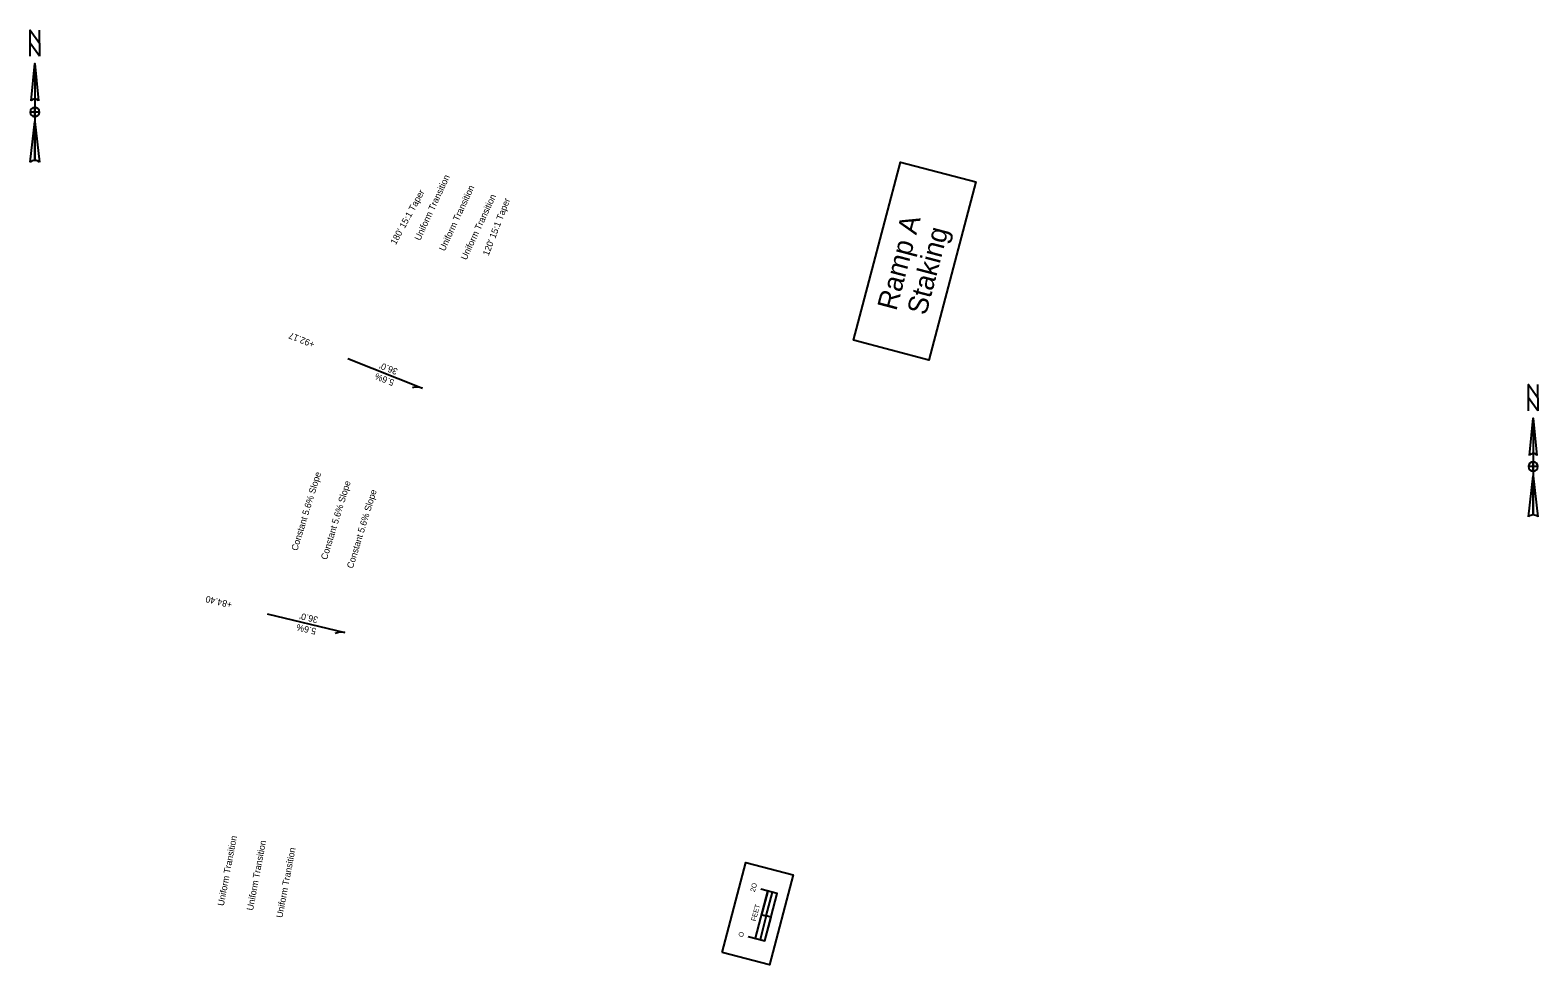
# Model space of a CAD drawing. Extents: x 20506035 to 20507470, y 7969245 to 7972296.
# Drawn here: x 20506164 to 20506780, y 7970799 to 7971181 of the extents above; entities that cross this region are included whole.
import ezdxf

# ---------------------------------------------------------------- set-up
doc = ezdxf.new("R2010")
doc.units = 0
for name, color, linetype in [('_CIVIL_CONSTRUCTION', 7, 'Continuous'), ('dsnStdShading', 7, 'Continuous'), ('EdgeShoulder', 7, 'Continuous')]:
    doc.layers.add(name, color=color, linetype=linetype)

msp = doc.modelspace()

# ---------------------------------------------------------------- linework, layer by layer
at = {"layer": '_CIVIL_CONSTRUCTION'}
for p, q in [((20506293.88, 7971047.06), (20506324.29, 7971034.93)), ((20506260.84, 7970942.77), (20506292.66, 7970935.05)), ((20506466.81, 7970818.74), (20506462.95, 7970819.75)), ((20506466.81, 7970818.74), (20506462.95, 7970819.75))]:
    msp.add_line(p, q, dxfattribs=at)
for points in [[(20506446.89, 7970804.33), (20506456.56, 7970841.08), (20506475.91, 7970835.99), (20506466.23, 7970799.24)], [(20506446.89, 7970804.33), (20506456.56, 7970841.08), (20506475.91, 7970835.99), (20506466.23, 7970799.24)], [(20506464.87, 7970819.25), (20506467.41, 7970828.92), (20506465.49, 7970829.42), (20506462.95, 7970819.75)], [(20506464.27, 7970809.06), (20506466.81, 7970818.74), (20506464.87, 7970819.25), (20506462.32, 7970809.58)]]:
    msp.add_lwpolyline(points, close=True, dxfattribs=at)
for points in [[(20506457.5, 7970810.85), (20506464.27, 7970809.06), (20506469.36, 7970828.41), (20506462.59, 7970830.19)], [(20506460.4, 7970810.08), (20506465.49, 7970829.42)]]:
    msp.add_lwpolyline(points, dxfattribs=at)
for centre, start, end in [((20506322, 7971029.2), 68.21951, 106.42255), ((20506291.2, 7970929.06), 76.34017, 114.5432)]:
    msp.add_arc(centre, 6.16, start, end, dxfattribs=at)
at = {"layer": 'dsnStdShading'}
for points in [[(20506550.48, 7971119.28), (20506531.31, 7971046.44), (20506500.55, 7971054.54), (20506519.72, 7971127.37)], [(20506500.55, 7971054.54), (20506519.72, 7971127.37), (20506550.48, 7971119.28), (20506531.31, 7971046.44)]]:
    msp.add_lwpolyline(points, close=True, dxfattribs=at)
at = {"layer": 'EdgeShoulder'}
for p, q in [((20506165.89, 7971167.58), (20506167.41, 7971152.37)), ((20506165.89, 7971167.58), (20506165.89, 7971128.03)), ((20506164.37, 7971152.37), (20506164.37, 7971152.37)), ((20506164.43, 7971152.51), (20506164.71, 7971152.83)), ((20506163.99, 7971127.27), (20506165.89, 7971144)), ((20506165.89, 7971145.91), (20506165.89, 7971145.91)), ((20506778.32, 7971022.69), (20506779.84, 7971007.48)), ((20506778.32, 7971022.69), (20506778.32, 7970983.14)), ((20506776.85, 7971007.62), (20506777.14, 7971007.93)), ((20506776.8, 7971007.48), (20506776.79, 7971007.48)), ((20506776.41, 7970982.37), (20506778.32, 7970999.11)), ((20506778.32, 7971001.01), (20506778.32, 7971001.01))]:
    msp.add_line(p, q, dxfattribs=at)
for points in [[(20506167.79, 7971170.63), (20506163.99, 7971175.95), (20506163.99, 7971181.27), (20506167.79, 7971175.95)], [(20506780.22, 7971025.73), (20506776.41, 7971031.05), (20506776.41, 7971036.38), (20506780.22, 7971031.05)]]:
    msp.add_lwpolyline(points, close=True, dxfattribs=at)
for points in [[(20506163.99, 7971170.63), (20506163.99, 7971181.27), (20506167.79, 7971175.95), (20506167.79, 7971181.27)], [(20506164.37, 7971152.37), (20506165.89, 7971167.58), (20506165.89, 7971153.13)], [(20506167.79, 7971147.81), (20506165.89, 7971147.81), (20506165.89, 7971149.71)], [(20506165.89, 7971145.91), (20506165.89, 7971147.81), (20506163.99, 7971147.81)], [(20506165.89, 7971128.03), (20506165.89, 7971144), (20506167.79, 7971127.27)], [(20506776.41, 7971025.73), (20506776.41, 7971036.38), (20506780.22, 7971031.05), (20506780.22, 7971036.38)], [(20506776.79, 7971007.48), (20506778.32, 7971022.69), (20506778.32, 7971008.24)], [(20506778.32, 7971001.01), (20506778.32, 7971002.91), (20506776.41, 7971002.91)], [(20506780.22, 7971002.91), (20506778.32, 7971002.91), (20506778.32, 7971004.81)], [(20506778.32, 7970983.14), (20506778.32, 7970999.11), (20506780.22, 7970982.38)]]:
    msp.add_lwpolyline(points, dxfattribs=at)
for centre, radius, start, end in [((20506165.89, 7971147.81), 1.9, 90, 180), ((20506165.89, 7971151.23), 1.9, 90.02039, 143.12574), ((20506165.89, 7971151.23), 1.9, 36.84806, 90.02184), ((20506165.89, 7971147.81), 1.9, 0, 90), ((20506165.89, 7971147.81), 1.9, 180, 270), ((20506165.89, 7971147.81), 1.9, 270, 360), ((20506165.89, 7971125.28), 2.76, 89.98939, 133.61895), ((20506165.89, 7971125.27), 2.76, 46.40206, 90.00064), ((20506778.32, 7971006.33), 1.9, 90.02039, 143.12574), ((20506778.32, 7971006.34), 1.9, 36.84806, 90.02184), ((20506778.32, 7971002.91), 1.9, 90, 180), ((20506778.32, 7971002.91), 1.9, 180, 270), ((20506778.32, 7971002.91), 1.9, 0, 90), ((20506778.32, 7971002.91), 1.9, 270, 360), ((20506778.32, 7970980.38), 2.76, 89.98939, 133.61895), ((20506778.32, 7970980.38), 2.76, 46.40206, 90.00064)]:
    msp.add_arc(centre, radius, start, end, dxfattribs=at)

# ---------------------------------------------------------------- texts
at = {"layer": '_CIVIL_CONSTRUCTION'}
for s, height, rotation, p in [('Uniform Transition', 2.664, 65.10112, (20506323.37, 7971095.03)), ("180' 15:1 Taper", 2.664, 61.46425, (20506313.43, 7971093.35)), ('Uniform Transition', 2.664, 65.10112, (20506333.41, 7971090.73)), ('Uniform Transition', 2.664, 65.10112, (20506342.27, 7971087.09)), ("120' 15:1 Taper", 2.664, 69.03727, (20506351.35, 7971088.83)), ('+92.17', 2.664, 158.24576, (20506280.56, 7971053.81)), ("36.0'", 2.664, 158.34848, (20506314.49, 7971042.75)), ('5.6%', 2.664, 158.34848, (20506313.09, 7971038.23)), ('Constant 5.6% Slope', 2.664, 72.99314, (20506273.18, 7970968.26)), ('Constant 5.6% Slope', 2.664, 72.99314, (20506285.26, 7970964.62)), ('Constant 5.6% Slope', 2.664, 72.99314, (20506295.89, 7970961.05)), ('+84.40', 2.664, 166.36642, (20506246.77, 7970947.55)), ("36.0'", 2.664, 166.46914, (20506281.86, 7970941.41)), ('5.6%', 2.664, 166.46914, (20506281.11, 7970936.73)), ('Uniform Transition', 2.664, 79.27103, (20506243.14, 7970823.17)), ('Uniform Transition', 2.664, 79.27103, (20506255.06, 7970821.28)), ('Uniform Transition', 2.664, 79.27103, (20506267.09, 7970818.3)), ('2O', 2, 75.25231, (20506460.18, 7970828.89)), ('FEET', 2, 75.25231, (20506460.54, 7970816.89)), ('O', 2, 75.25231, (20506455.31, 7970810.4))]:
    msp.add_text(s, height=height, rotation=rotation, dxfattribs=at).set_placement(p)
at = {"layer": 'dsnStdShading'}
for s, p in [('Ramp A', (20506517.97, 7971066.26)), ('Staking', (20506530.14, 7971064.42))]:
    msp.add_text(s, height=8.16, rotation=75.25231, dxfattribs=at).set_placement(p)

doc.saveas('drawing.dxf')
